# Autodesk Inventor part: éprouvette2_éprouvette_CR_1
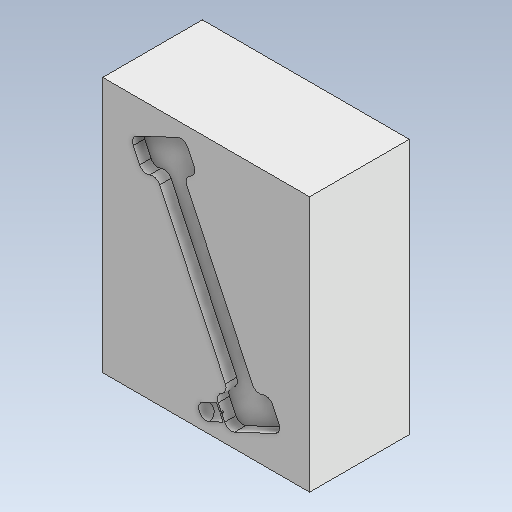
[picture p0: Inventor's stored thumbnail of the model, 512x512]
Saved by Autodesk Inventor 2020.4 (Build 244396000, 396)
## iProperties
Created: 2021-10
Part Number: éprouvette2_éprouvette_CR_1
Material: Générique
Document SubType Name: Modeling
Designer: mel
Density: 1 g/cm^3
Appearance: Par défaut
Author: mel
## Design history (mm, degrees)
node "éprouvette2_éprouvette_CR_Base"
feature "Sculpter1"
feature "Solide1::éprouvette2_éprouvette_CR_Base"
tag "FonctionRepérage1"
node "Solide1"
feature "éprouvette2_éprouvette_CR_Base_Corps"
feature "Surface1"
body "Srf1"
